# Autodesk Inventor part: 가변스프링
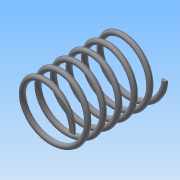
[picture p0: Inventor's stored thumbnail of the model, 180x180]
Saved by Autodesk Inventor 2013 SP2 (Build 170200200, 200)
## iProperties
Created: 2018-06
Part Number: 가변스프링
Material: 일반
Document SubType Name: Modeling
Designer: Administrator
Density: 1 g/cm^3
Author: Administrator
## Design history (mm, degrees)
sketch "스케치1"
  geometry: L1 (0, 0)-(0, 73.25); L2 (0, 0)-(22.5, 0); L3 (0, 73.25)-(22.5, 73.25); C1 r 2 at (22.5, 0)
  constraints: 6 end point, 1 centre point, 1 coincident, 1 parallel, 1 perpendicular, 1 vertical
  dimensions: "d0" = 73.25 distance of L1.start L1.end (derived); "d1" = 22.5 distance of L1.start L2.end; "d2" = 22.5 distance of L1.end L3.end; "d3" = 4 diameter of C1
feature "코일1" sketch "스케치1" pitch "d4" = 10; turns "d6" = 6; dims "d5" = 73.25 (= d0), "d7" = 0, angle "d8" = 90 deg, angle "d9" = 90 deg, "d10" = 0, "d11" = 0
sketch "스케치2"
  geometry: L1 (0, 25)-(73.25, 25); L2 (73.25, 25)-(73.25, -25); L3 (73.25, -25)-(0, -25); L4 (0, -25)-(0, 25); 2 further points
  constraints: 8 end point, 2 parallel, 1 coincident, 1 horizontal, 1 midpoint, 1 perpendicular
  dimensions: "d12" = 73.25 distance of L1.start L1.end (derived); "d14" = 50 distance of L1.end L2.end
extrude "돌출1" sketch "스케치2" stored distance "d15" = 50; taper "d16" = 0 deg
node "솔리드1"
